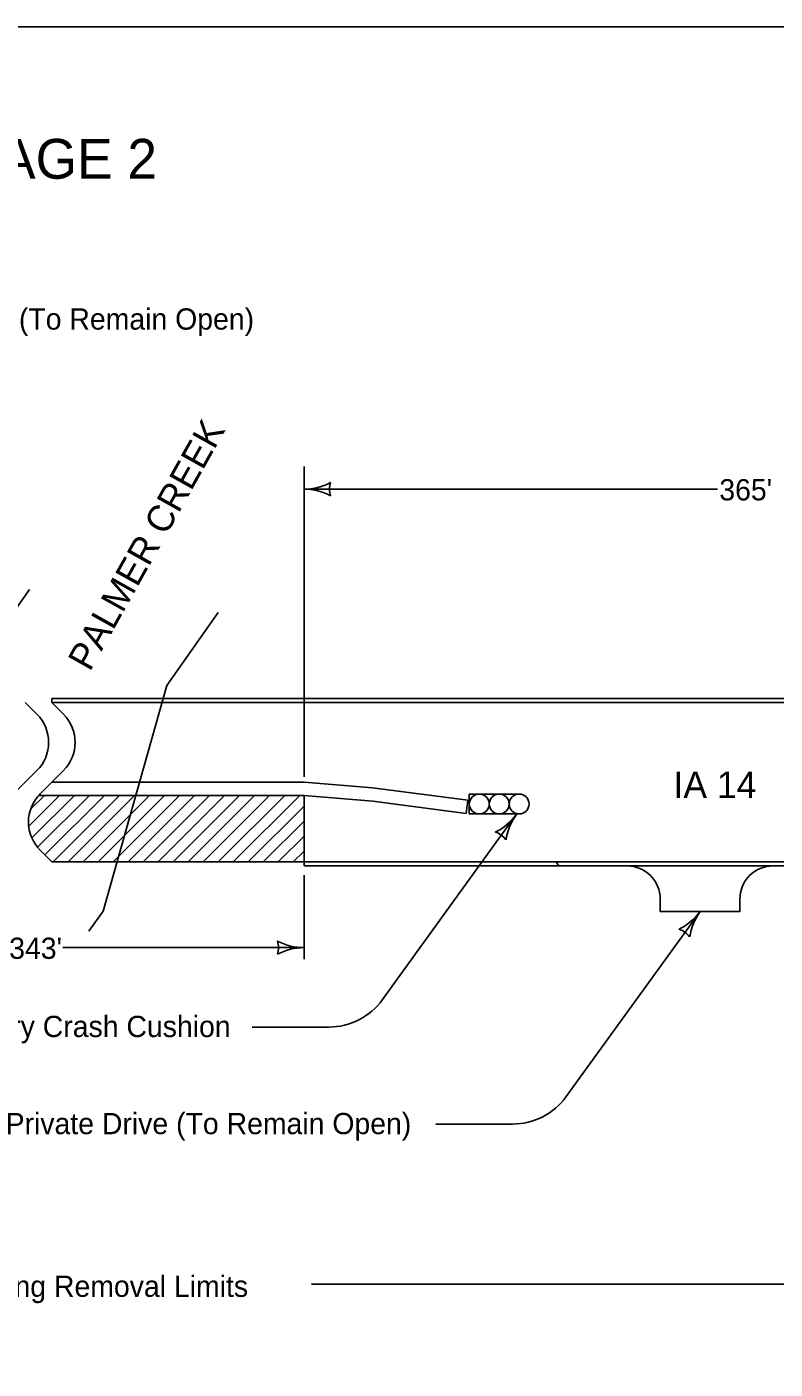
# Model space of a CAD drawing. Extents: x -2134934 to -2127057, y -2139046 to -2137036.
# Drawn here: x -2128679 to -2128115, y -2138047 to -2137036 of the extents above; entities that cross this region are included whole.
import ezdxf

# ---------------------------------------------------------------- set-up
doc = ezdxf.new("R2010")
doc.units = 0
for name, color, linetype in [('Barrier', 7, 'Continuous'), ('BridgeSuperStructureExisting', 7, 'Continuous'), ('Default', 7, 'Continuous'), ('dsnCellsNorthArrow', 7, 'Continuous'), ('DsnShtPlotIdentification', 7, 'Continuous'), ('DsnShtPlotShape', 7, 'Continuous')]:
    doc.layers.add(name, color=color, linetype=linetype)

msp = doc.modelspace()

# ---------------------------------------------------------------- linework, layer by layer
at = {"layer": 'BridgeSuperStructureExisting'}
for p, q in [((-2128470.1, -2137367.2), (-2128470.1, -2137601.1)), ((-2128158.6, -2137384.3), (-2128470.1, -2137384.3)), ((-2128680.1, -2137545.2), (-2128671.3, -2137553.9)), ((-2128671.3, -2137553.9), (-2128680.1, -2137545.2)), ((-2128660.1, -2137545.2), (-2128651.3, -2137553.9)), ((-2127160.1, -2137545.2), (-2128660.1, -2137545.2)), ((-2128660.1, -2137545.2), (-2128651.3, -2137553.9)), ((-2128671.3, -2137596.4), (-2128688.9, -2137613.9)), ((-2128651.3, -2137596.4), (-2128668.9, -2137613.9)), ((-2128651.3, -2137596.4), (-2128660.1, -2137605.2)), ((-2128660.1, -2137605.2), (-2128668.9, -2137613.9)), ((-2128470.1, -2137605.2), (-2128660.1, -2137605.2)), ((-2128470.1, -2137605.2), (-2128660.1, -2137605.2)), ((-2128660.1, -2137605.2), (-2128470.1, -2137605.2)), ((-2128660.1, -2137605.2), (-2128470.1, -2137605.2)), ((-2128418.6, -2137609.5), (-2128470.1, -2137605.2)), ((-2128470.1, -2137605.2), (-2128418.6, -2137609.5)), ((-2128470.1, -2137605.2), (-2128418.6, -2137609.5)), ((-2128654.4, -2137615.2), (-2128677.5, -2137638.3)), ((-2128665.7, -2137615.2), (-2128676.1, -2137625.6)), ((-2128643.1, -2137615.2), (-2128675.1, -2137647.2)), ((-2128631.8, -2137615.2), (-2128670.8, -2137654.2)), ((-2128670.1, -2137615.2), (-2128470.5, -2137615.2)), ((-2128670.1, -2137615.2), (-2128470.1, -2137615.2)), ((-2128620.4, -2137615.2), (-2128665.3, -2137660)), ((-2128609.1, -2137615.2), (-2128659.1, -2137665.2)), ((-2128597.8, -2137615.2), (-2128647.8, -2137665.2)), ((-2128586.5, -2137615.2), (-2128636.5, -2137665.2)), ((-2128575.2, -2137615.2), (-2128625.2, -2137665.2)), ((-2128563.9, -2137615.2), (-2128613.9, -2137665.2)), ((-2128552.6, -2137615.2), (-2128602.6, -2137665.2)), ((-2128591.2, -2137665.2), (-2128541.2, -2137615.2)), ((-2128529.9, -2137615.2), (-2128579.9, -2137665.2)), ((-2128518.6, -2137615.2), (-2128568.6, -2137665.2)), ((-2128507.3, -2137615.2), (-2128557.3, -2137665.2)), ((-2128496, -2137615.2), (-2128546, -2137665.2)), ((-2128484.7, -2137615.2), (-2128534.7, -2137665.2)), ((-2128473.4, -2137615.2), (-2128523.4, -2137665.2)), ((-2128470.5, -2137615.2), (-2128470.4, -2137615.2)), ((-2128470.4, -2137615.2), (-2128470.1, -2137615.2)), ((-2128470.1, -2137615.2), (-2128470.1, -2137665.2)), ((-2128470.1, -2137615.2), (-2128470.1, -2137615.2)), ((-2128470.1, -2137615.2), (-2128418.4, -2137619.5)), ((-2128470.1, -2137615.2), (-2128418.4, -2137619.5)), ((-2128418.4, -2137619.5), (-2128470.1, -2137615.2)), ((-2128470.1, -2137615.2), (-2128470.1, -2137665.2)), ((-2128346.6, -2137618.8), (-2128418.6, -2137609.5)), ((-2128346.6, -2137618.8), (-2128418.6, -2137609.5)), ((-2128418.6, -2137609.5), (-2128346.6, -2137618.8)), ((-2128418.6, -2137609.5), (-2128346.6, -2137618.8)), ((-2128345.6, -2137629.1), (-2128345.6, -2137614.1)), ((-2128345.6, -2137614.1), (-2128308.1, -2137614.1)), ((-2128345.6, -2137629.1), (-2128345.6, -2137614.1)), ((-2128345.6, -2137614.1), (-2128308.1, -2137614.1)), ((-2128470.1, -2137623.2), (-2128512.1, -2137665.2)), ((-2128418.4, -2137619.5), (-2128347.9, -2137628.7)), ((-2128418.4, -2137619.5), (-2128347.9, -2137628.7)), ((-2128347.9, -2137628.7), (-2128418.4, -2137619.5)), ((-2128347.9, -2137628.7), (-2128346.6, -2137618.8)), ((-2128346.6, -2137618.8), (-2128347.9, -2137628.7)), ((-2128346.6, -2137618.8), (-2128347.9, -2137628.7)), ((-2128470.1, -2137634.5), (-2128500.8, -2137665.2)), ((-2128310.2, -2137629.5), (-2128411, -2137769)), ((-2128308.1, -2137629.1), (-2128345.6, -2137629.1)), ((-2128308.1, -2137629.1), (-2128345.6, -2137629.1)), ((-2128470.1, -2137645.8), (-2128489.5, -2137665.2)), ((-2128668.9, -2137656.4), (-2128660.1, -2137665.2)), ((-2128470.1, -2137657.1), (-2128478.2, -2137665.2)), ((-2128470.1, -2137665.2), (-2127160.1, -2137665.2)), ((-2128470.1, -2137675.2), (-2128470.1, -2137738.5)), ((-2128116.8, -2137668.2), (-2128226.8, -2137668.2)), ((-2128171.8, -2137702.6), (-2128272.6, -2137842.1)), ((-2128470.1, -2137729.8), (-2128651.7, -2137729.8)), ((-2128451.5, -2137789.7), (-2128509.3, -2137789.7)), ((-2128313.1, -2137862.8), (-2128370.9, -2137862.8)), ((-2127805.1, -2137983.3), (-2128464.5, -2137983.3))]:
    msp.add_line(p, q, dxfattribs=at)
for points in [[(-2128677, -2137459.9), (-2128715.6, -2137514.8), (-2128763.5, -2137684.9), (-2128785.5, -2137714.7)], [(-2128534.7, -2137477.4), (-2128573.4, -2137532.3), (-2128621.3, -2137702.4), (-2128632.3, -2137717.3)], [(-2128680.1, -2137605.2), (-2128680.1, -2137605.2), (-2128671.3, -2137596.4)], [(-2128660.1, -2137605.2), (-2128660.1, -2137605.2)], [(-2128660.1, -2137605.2), (-2128660.1, -2137605.2)], [(-2128470.5, -2137615.2), (-2128470.5, -2137615.2)], [(-2128308.1, -2137614.1), (-2128308.1, -2137614.1)], [(-2128308.1, -2137629.1), (-2128308.1, -2137629.1)], [(-2128470.1, -2137665.2), (-2128660.1, -2137665.2)], [(-2128201.8, -2137693.2), (-2128201.8, -2137702.6), (-2128141.8, -2137702.6), (-2128141.8, -2137693.2)]]:
    msp.add_lwpolyline(points, dxfattribs=at)
for centre in [(-2128338.1, -2137621.6), (-2128338.1, -2137621.6), (-2128323.1, -2137621.6), (-2128323.1, -2137621.6), (-2128308.1, -2137621.6), (-2128308.1, -2137621.6)]:
    msp.add_circle(centre, 7.5, dxfattribs=at)
for centre, radius, start, end in [((-2128692.5, -2137575.2), 30, 315, 45), ((-2128692.5, -2137575.2), 30, 315, 45), ((-2128672.5, -2137575.2), 30, 315, 45), ((-2128672.5, -2137575.2), 30, 315, 45), ((-2128647.7, -2137635.2), 30, 135, 225), ((-2128647.7, -2137635.2), 30, 135, 138.1884), ((-2128308.1, -2137621.6), 7.5, 270.0028, 89.9972), ((-2128226.8, -2137693.2), 25, 0, 90), ((-2128116.8, -2137693.2), 25, 90, 180), ((-2128505.8, -2137729.8), 16.4, 342.2666, 17.7334), ((-2128470.1, -2137687.4), 42.5, 241.9275, 270), ((-2128470.1, -2137772.3), 42.5, 90, 118.0725), ((-2128451.5, -2137739.7), 50, 270, 324.138), ((-2128313.1, -2137812.8), 50, 270, 324.138)]:
    msp.add_arc(centre, radius, start, end, dxfattribs=at)
at = {"layer": 'Default'}
msp.add_lwpolyline([(-2130232, -2137035.9), (-2127097, -2137035.9), (-2127097, -2139045.9), (-2130232, -2139045.9)], close=True, dxfattribs=at)
at = {"layer": 'DsnShtPlotIdentification'}
for p, q in [((-2127160.1, -2137542.2), (-2128660.1, -2137542.2)), ((-2127160.1, -2137542.2), (-2128660.1, -2137542.2)), ((-2128660.1, -2137542.2), (-2128660.1, -2137545.2)), ((-2127160.1, -2137545.2), (-2128660.1, -2137545.2)), ((-2128660.1, -2137545.2), (-2127810.1, -2137545.2)), ((-2128660.1, -2137665.2), (-2127159.5, -2137665.2)), ((-2128470.1, -2137665.2), (-2128470.1, -2137668.2)), ((-2128470.1, -2137668.2), (-2128470.1, -2137665.2)), ((-2128278.1, -2137668.2), (-2128280.3, -2137665.2)), ((-2128280.3, -2137665.2), (-2128278.1, -2137668.2)), ((-2127805.1, -2137665.2), (-2128280.3, -2137665.2)), ((-2128470.1, -2137668.2), (-2128278.1, -2137668.2)), ((-2128278.1, -2137668.2), (-2127805.1, -2137668.2))]:
    msp.add_line(p, q, dxfattribs=at)
for points in [[(-2128471.3, -2137545.2), (-2127158.8, -2137545.2)], [(-2127160.1, -2137665.2), (-2128470.1, -2137665.2)], [(-2128280.3, -2137665.2), (-2128469.7, -2137665.2), (-2128470.1, -2137665.2)], [(-2127160.1, -2137668.2), (-2128470.1, -2137668.2)]]:
    msp.add_lwpolyline(points, dxfattribs=at)
at = {"layer": 'DsnShtPlotShape'}
for centre, radius, start, end in [((-2128470.1, -2137341.8), 42.5, 270, 298.0725), ((-2128434.5, -2137384.3), 16.4, 162.2666, 197.7334), ((-2128470.1, -2137426.8), 42.5, 61.9275, 90), ((-2128344.4, -2137604.4), 42.5, 295.6285, 323.701), ((-2128275.9, -2137654.7), 42.5, 143.701, 171.7735), ((-2128331.3, -2137658.2), 16.4, 35.9676, 71.4343), ((-2128206, -2137677.5), 42.5, 295.6285, 323.701), ((-2128137.5, -2137727.8), 42.5, 143.701, 171.7735), ((-2128192.9, -2137731.4), 16.4, 35.9676, 71.4343)]:
    msp.add_arc(centre, radius, start, end, dxfattribs=at)

# ---------------------------------------------------------------- texts
at = {"layer": 'Barrier'}
msp.add_text('STAGE 2', height=30, dxfattribs=at).set_placement((-2128750.3, -2137150.4))
at = {"layer": 'BridgeSuperStructureExisting'}
for s, p in [('Private Drive (To Remain Open)', (-2128813.3, -2137264.1)), ("365'", (-2128157.3, -2137392.8)), ("343'", (-2128692.2, -2137738.3)), ('Temporary Crash Cushion', (-2128776.3, -2137797.2)), ('Private Drive (To Remain Open)', (-2128694.9, -2137870.4)), ('Pavement Marking Removal Limits', (-2128842.8, -2137993))]:
    msp.add_text(s, height=16, dxfattribs=at).set_placement(p)
at = {"layer": 'dsnCellsNorthArrow'}
msp.add_text('PALMER CREEK', height=20, rotation=60.7624, dxfattribs=at).set_placement((-2128631.4, -2137522.4))
msp.add_text('IA 14', height=20, dxfattribs=at).set_placement((-2128191.8, -2137617.1))

doc.saveas('drawing.dxf')
